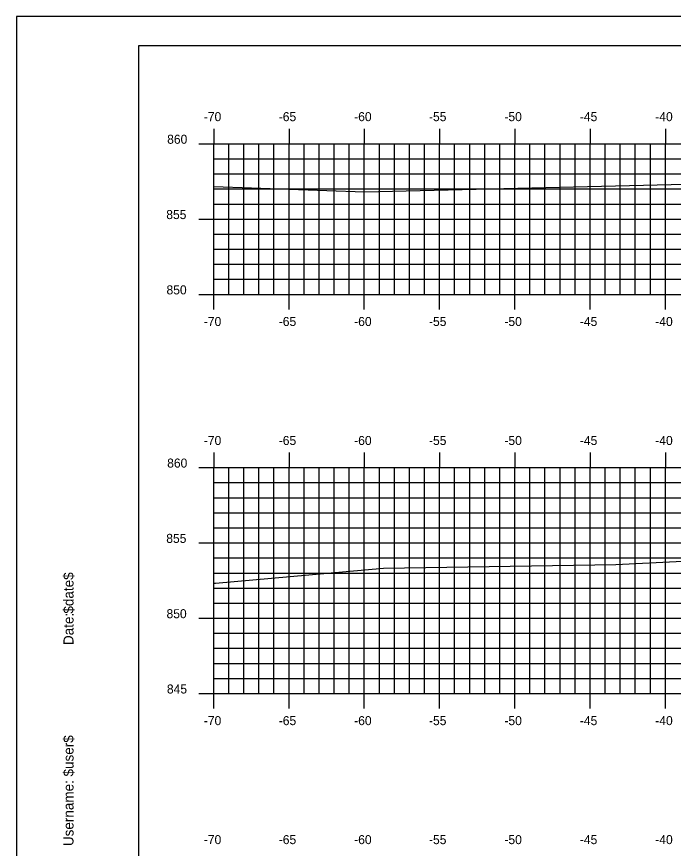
# Model space of a CAD drawing. Extents: x 2194738 to 2195190, y 863888 to 863998.
# Drawn here: x 2194837.2 to 2194880.8, y 863943.2 to 863998.4 of the extents above; entities that cross this region are included whole.
import ezdxf

# ---------------------------------------------------------------- set-up
doc = ezdxf.new("R2010")
doc.units = 0
for name, color, linetype in [('BORDER', 7, 'Continuous'), ('H_V ANNOTATION', 7, 'Continuous'), ('MAJOR', 7, 'Continuous'), ('MINOR', 7, 'Continuous'), ('PLOT BOUNDARY', 7, 'Continuous'), ('S_Roadway_Centerline', 7, 'Continuous')]:
    doc.layers.add(name, color=color, linetype=linetype)

msp = doc.modelspace()

# ---------------------------------------------------------------- linework, layer by layer
at = {"layer": 'BORDER'}
msp.add_lwpolyline([(2194845.256, 863891.446), (2195005.256, 863891.446), (2195005.256, 863996.446), (2194845.256, 863996.446)], close=True, dxfattribs=at)
at = {"layer": 'MAJOR'}
for p, q in [((2194850.256, 863990.948), (2194850.256, 863989.946)), ((2194855.256, 863990.948), (2194855.256, 863989.946)), ((2194860.256, 863990.948), (2194860.256, 863989.946)), ((2194865.256, 863990.948), (2194865.256, 863989.946)), ((2194870.256, 863990.948), (2194870.256, 863989.946)), ((2194875.256, 863990.948), (2194875.256, 863989.946)), ((2194880.256, 863990.948), (2194880.256, 863989.946)), ((2194849.254, 863989.946), (2194850.256, 863989.946)), ((2194850.256, 863989.946), (2194990.256, 863989.946)), ((2194850.256, 863979.946), (2194850.256, 863989.946)), ((2194850.256, 863979.946), (2194850.256, 863989.946)), ((2194855.256, 863979.946), (2194855.256, 863989.946)), ((2194860.256, 863979.946), (2194860.256, 863989.946)), ((2194865.256, 863979.946), (2194865.256, 863989.946)), ((2194870.256, 863979.946), (2194870.256, 863989.946)), ((2194875.256, 863979.946), (2194875.256, 863989.946)), ((2194880.256, 863979.946), (2194880.256, 863989.946)), ((2194849.254, 863984.946), (2194850.256, 863984.946)), ((2194850.256, 863984.946), (2194990.256, 863984.946)), ((2194849.254, 863979.946), (2194850.256, 863979.946)), ((2194850.256, 863979.946), (2194990.256, 863979.946)), ((2194850.256, 863978.944), (2194850.256, 863979.946)), ((2194855.256, 863978.944), (2194855.256, 863979.946)), ((2194860.256, 863978.944), (2194860.256, 863979.946)), ((2194865.256, 863978.944), (2194865.256, 863979.946)), ((2194870.256, 863978.944), (2194870.256, 863979.946)), ((2194875.256, 863978.944), (2194875.256, 863979.946)), ((2194880.256, 863978.944), (2194880.256, 863979.946)), ((2194850.256, 863969.448), (2194850.256, 863968.446)), ((2194855.256, 863969.448), (2194855.256, 863968.446)), ((2194860.256, 863969.448), (2194860.256, 863968.446)), ((2194865.256, 863969.448), (2194865.256, 863968.446)), ((2194870.256, 863969.448), (2194870.256, 863968.446)), ((2194875.256, 863969.448), (2194875.256, 863968.446)), ((2194880.256, 863969.448), (2194880.256, 863968.446)), ((2194849.254, 863968.446), (2194850.256, 863968.446)), ((2194850.256, 863968.446), (2194990.256, 863968.446)), ((2194850.256, 863953.446), (2194850.256, 863968.446)), ((2194850.256, 863953.446), (2194850.256, 863968.446)), ((2194855.256, 863953.446), (2194855.256, 863968.446)), ((2194860.256, 863953.446), (2194860.256, 863968.446)), ((2194865.256, 863953.446), (2194865.256, 863968.446)), ((2194870.256, 863953.446), (2194870.256, 863968.446)), ((2194875.256, 863953.446), (2194875.256, 863968.446)), ((2194880.256, 863953.446), (2194880.256, 863968.446)), ((2194849.254, 863963.446), (2194850.256, 863963.446)), ((2194850.256, 863963.446), (2194990.256, 863963.446)), ((2194849.254, 863958.446), (2194850.256, 863958.446)), ((2194850.256, 863958.446), (2194990.256, 863958.446)), ((2194849.254, 863953.446), (2194850.256, 863953.446)), ((2194850.256, 863953.446), (2194990.256, 863953.446)), ((2194850.256, 863952.444), (2194850.256, 863953.446)), ((2194855.256, 863952.444), (2194855.256, 863953.446)), ((2194860.256, 863952.444), (2194860.256, 863953.446)), ((2194865.256, 863952.444), (2194865.256, 863953.446)), ((2194870.256, 863952.444), (2194870.256, 863953.446)), ((2194875.256, 863952.444), (2194875.256, 863953.446)), ((2194880.256, 863952.444), (2194880.256, 863953.446))]:
    msp.add_line(p, q, dxfattribs=at)
at = {"layer": 'MINOR'}
for p, q in [((2194851.256, 863979.946), (2194851.256, 863989.946)), ((2194852.256, 863979.946), (2194852.256, 863989.946)), ((2194853.256, 863979.946), (2194853.256, 863989.946)), ((2194854.256, 863979.946), (2194854.256, 863989.946)), ((2194856.256, 863979.946), (2194856.256, 863989.946)), ((2194857.256, 863979.946), (2194857.256, 863989.946)), ((2194858.256, 863979.946), (2194858.256, 863989.946)), ((2194859.256, 863979.946), (2194859.256, 863989.946)), ((2194861.256, 863979.946), (2194861.256, 863989.946)), ((2194862.256, 863979.946), (2194862.256, 863989.946)), ((2194863.256, 863979.946), (2194863.256, 863989.946)), ((2194864.256, 863979.946), (2194864.256, 863989.946)), ((2194866.256, 863979.946), (2194866.256, 863989.946)), ((2194867.256, 863979.946), (2194867.256, 863989.946)), ((2194868.256, 863979.946), (2194868.256, 863989.946)), ((2194869.256, 863979.946), (2194869.256, 863989.946)), ((2194871.256, 863979.946), (2194871.256, 863989.946)), ((2194872.256, 863979.946), (2194872.256, 863989.946)), ((2194873.256, 863979.946), (2194873.256, 863989.946)), ((2194874.256, 863979.946), (2194874.256, 863989.946)), ((2194876.256, 863979.946), (2194876.256, 863989.946)), ((2194877.256, 863979.946), (2194877.256, 863989.946)), ((2194878.256, 863979.946), (2194878.256, 863989.946)), ((2194879.256, 863979.946), (2194879.256, 863989.946)), ((2194850.256, 863988.946), (2194990.256, 863988.946)), ((2194850.256, 863988.946), (2194851.258, 863988.946)), ((2194850.256, 863987.946), (2194990.256, 863987.946)), ((2194850.256, 863987.946), (2194851.258, 863987.946)), ((2194850.256, 863986.946), (2194990.256, 863986.946)), ((2194850.256, 863986.946), (2194851.258, 863986.946)), ((2194850.256, 863985.946), (2194990.256, 863985.946)), ((2194850.256, 863985.946), (2194851.258, 863985.946)), ((2194850.256, 863983.946), (2194990.256, 863983.946)), ((2194850.256, 863983.946), (2194851.258, 863983.946)), ((2194850.256, 863982.946), (2194990.256, 863982.946)), ((2194850.256, 863982.946), (2194851.258, 863982.946)), ((2194850.256, 863981.946), (2194990.256, 863981.946)), ((2194850.256, 863981.946), (2194851.258, 863981.946)), ((2194850.256, 863980.946), (2194990.256, 863980.946)), ((2194850.256, 863980.946), (2194851.258, 863980.946)), ((2194851.256, 863953.446), (2194851.256, 863968.446)), ((2194852.256, 863953.446), (2194852.256, 863968.446)), ((2194853.256, 863953.446), (2194853.256, 863968.446)), ((2194854.256, 863953.446), (2194854.256, 863968.446)), ((2194856.256, 863953.446), (2194856.256, 863968.446)), ((2194857.256, 863953.446), (2194857.256, 863968.446)), ((2194858.256, 863953.446), (2194858.256, 863968.446)), ((2194859.256, 863953.446), (2194859.256, 863968.446)), ((2194861.256, 863953.446), (2194861.256, 863968.446)), ((2194862.256, 863953.446), (2194862.256, 863968.446)), ((2194863.256, 863953.446), (2194863.256, 863968.446)), ((2194864.256, 863953.446), (2194864.256, 863968.446)), ((2194866.256, 863953.446), (2194866.256, 863968.446)), ((2194867.256, 863953.446), (2194867.256, 863968.446)), ((2194868.256, 863953.446), (2194868.256, 863968.446)), ((2194869.256, 863953.446), (2194869.256, 863968.446)), ((2194871.256, 863953.446), (2194871.256, 863968.446)), ((2194872.256, 863953.446), (2194872.256, 863968.446)), ((2194873.256, 863953.446), (2194873.256, 863968.446)), ((2194874.256, 863953.446), (2194874.256, 863968.446)), ((2194876.256, 863953.446), (2194876.256, 863968.446)), ((2194877.256, 863953.446), (2194877.256, 863968.446)), ((2194878.256, 863953.446), (2194878.256, 863968.446)), ((2194879.256, 863953.446), (2194879.256, 863968.446)), ((2194850.256, 863967.446), (2194990.256, 863967.446)), ((2194850.256, 863967.446), (2194851.258, 863967.446)), ((2194850.256, 863966.446), (2194990.256, 863966.446)), ((2194850.256, 863966.446), (2194851.258, 863966.446)), ((2194850.256, 863965.446), (2194990.256, 863965.446)), ((2194850.256, 863965.446), (2194851.258, 863965.446)), ((2194850.256, 863964.446), (2194990.256, 863964.446)), ((2194850.256, 863964.446), (2194851.258, 863964.446)), ((2194850.256, 863962.446), (2194990.256, 863962.446)), ((2194850.256, 863962.446), (2194851.258, 863962.446)), ((2194850.256, 863961.446), (2194990.256, 863961.446)), ((2194850.256, 863961.446), (2194851.258, 863961.446)), ((2194850.256, 863960.446), (2194990.256, 863960.446)), ((2194850.256, 863960.446), (2194851.258, 863960.446)), ((2194850.256, 863959.446), (2194990.256, 863959.446)), ((2194850.256, 863959.446), (2194851.258, 863959.446)), ((2194850.256, 863957.446), (2194990.256, 863957.446)), ((2194850.256, 863957.446), (2194851.258, 863957.446)), ((2194850.256, 863956.446), (2194990.256, 863956.446)), ((2194850.256, 863956.446), (2194851.258, 863956.446)), ((2194850.256, 863955.446), (2194990.256, 863955.446)), ((2194850.256, 863955.446), (2194851.258, 863955.446)), ((2194850.256, 863954.446), (2194990.256, 863954.446)), ((2194850.256, 863954.446), (2194851.258, 863954.446))]:
    msp.add_line(p, q, dxfattribs=at)
at = {"layer": 'PLOT BOUNDARY'}
msp.add_lwpolyline([(2194837.163, 863888.387), (2195007.163, 863888.387), (2195007.163, 863998.387), (2194837.163, 863998.387)], close=True, dxfattribs=at)
at = {"layer": 'S_Roadway_Centerline'}
for points in [[(2194850.256, 863987.118), (2194860.261, 863986.744), (2194881.56, 863987.272), (2194888.117, 863986.589), (2194891.093, 863986.502), (2194896.484, 863985.581), (2194896.738, 863985.651), (2194904.658, 863987.861), (2194905.389, 863987.998), (2194906.976, 863988.228), (2194907.657, 863988.272), (2194908.761, 863988.335), (2194918.129, 863988.439), (2194920.559, 863988.499), (2194922.869, 863988.473), (2194931.932, 863988.365), (2194932.412, 863988.339), (2194934.683, 863988.238), (2194936.777, 863987.806), (2194937.247, 863987.707), (2194941.272, 863986.538), (2194945.71, 863985.269)], [(2194850.256, 863960.77), (2194850.369, 863960.779), (2194861.52, 863961.766), (2194876.966, 863962.008), (2194890.309, 863962.671), (2194893.043, 863962.279), (2194895.447, 863962.079), (2194898.937, 863963.066), (2194903.925, 863964.628), (2194904.608, 863964.7), (2194905.482, 863964.826), (2194907.816, 863964.965), (2194908.574, 863965.008), (2194911.879, 863965.044), (2194920.431, 863965.259), (2194928.562, 863965.165), (2194931.945, 863965.125), (2194933.584, 863965.035), (2194934.433, 863964.997), (2194935.214, 863964.836), (2194936.848, 863964.491), (2194941.149, 863963.242), (2194946.41, 863961.523)]]:
    msp.add_lwpolyline(points, dxfattribs=at)

# ---------------------------------------------------------------- texts
at = {"layer": 'BORDER'}
for s, p in [('$date$', (2194840.941, 863958.751)), ('Date:', (2194840.941, 863956.663)), ('$user$', (2194840.941, 863947.937)), ('Username:', (2194840.941, 863943.314))]:
    msp.add_text(s, height=0.6696, rotation=90, dxfattribs=at).set_placement(p)
at = {"layer": 'H_V ANNOTATION'}
for s, p in [('-70', (2194849.597, 863991.446)), ('-65', (2194854.573, 863991.446)), ('-60', (2194859.582, 863991.446)), ('-55', (2194864.552, 863991.446)), ('-50', (2194869.56, 863991.446)), ('-45', (2194874.573, 863991.446)), ('-40', (2194879.582, 863991.446)), ('860', (2194847.161, 863989.946)), ('855', (2194847.102, 863984.946)), ('850', (2194847.118, 863979.946)), ('-70', (2194849.597, 863977.846)), ('-65', (2194854.573, 863977.846)), ('-60', (2194859.582, 863977.846)), ('-55', (2194864.552, 863977.846)), ('-50', (2194869.56, 863977.846)), ('-45', (2194874.573, 863977.846)), ('-40', (2194879.582, 863977.846)), ('-70', (2194849.597, 863969.946)), ('-65', (2194854.573, 863969.946)), ('-60', (2194859.582, 863969.946)), ('-55', (2194864.552, 863969.946)), ('-50', (2194869.56, 863969.946)), ('-45', (2194874.573, 863969.946)), ('-40', (2194879.582, 863969.946)), ('860', (2194847.161, 863968.446)), ('855', (2194847.102, 863963.446)), ('850', (2194847.118, 863958.446)), ('845', (2194847.145, 863953.446)), ('-70', (2194849.597, 863951.346)), ('-65', (2194854.573, 863951.346)), ('-60', (2194859.582, 863951.346)), ('-55', (2194864.552, 863951.346)), ('-50', (2194869.56, 863951.346)), ('-45', (2194874.573, 863951.346)), ('-40', (2194879.582, 863951.346)), ('-70', (2194849.597, 863943.446)), ('-65', (2194854.573, 863943.446)), ('-60', (2194859.582, 863943.446)), ('-55', (2194864.552, 863943.446)), ('-50', (2194869.56, 863943.446)), ('-45', (2194874.573, 863943.446)), ('-40', (2194879.582, 863943.446))]:
    msp.add_text(s, height=0.6, dxfattribs=at).set_placement(p)

doc.saveas('drawing.dxf')
